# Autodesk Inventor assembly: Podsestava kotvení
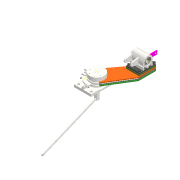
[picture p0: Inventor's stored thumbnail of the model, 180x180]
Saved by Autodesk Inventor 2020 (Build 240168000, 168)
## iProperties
Created: 2025-04
Part Number: Podsestava kotvení
Document SubType Name: Assembly
Designer: doma
Author: doma
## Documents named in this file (13)
- C:\Users\doma\Desktop\Pásovka záloha\Workgroups\NotInProject\Podsestava kotvení.iam
- C:\Users\doma\Desktop\Pásovka záloha\Workgroups\NotInProject\Deska kotevní.ipt
- C:\Users\doma\Desktop\Pásovka záloha\Workgroups\NotInProject\Středící kroužek.ipt
- C:\Users\doma\Desktop\Pásovka záloha\Workgroups\NotInProject\Doraz otočný.ipt
- C:\Users\doma\Desktop\Pásovka záloha\Workgroups\NotInProject\Svařenec horní části středu.iam
- C:\Users\doma\Desktop\Pásovka záloha\Workgroups\NotInProject\Domeček ax ložiska středu.ipt
- C:\Users\doma\Desktop\Pásovka záloha\Workgroups\NotInProject\Matice  středu.ipt
- C:\Users\doma\Desktop\Pásovka záloha\Workgroups\NotInProject\Tyč.ipt
- C:\Users\doma\Documents\Inventor\Content Center Files\R2020\cs-CZ\ISO 4762(2)\ISO 4762 - M5 x 30ISO.ipt
- C:\Users\doma\Desktop\Pásovka záloha\Workgroups\NotInProject\Podsestava otočné rameno.iam
- C:\Users\doma\Documents\Inventor\Content Center Files\R2020\cs-CZ\CSN 02 1741\CSN 02 1741 - 6.ipt
- C:\Users\doma\Desktop\Pásovka záloha\Libraries\Content Center Files\cs-CZ\CSN 02 4730\CSN 02 4730 - 511 04 - 20 x 35 x 10.ipt
- C:\Users\doma\Documents\Inventor\Content Center Files\R2020\cs-CZ\ISO 4762(2)\ISO 4762 - M6 x 45ISO.ipt
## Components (19 placed, 12 different names)
1. Deska kotevní:1 — Úhel:2, Proti sobě:17
2. Středící kroužek:1
3. Doraz otočný:1
4. Svařenec horní části středu:1 [sub-assembly] — Proti sobě:18
5. Domeček ax ložiska středu:1 — Proti sobě:19
6. Matice  středu:1
7. Tyč:1
8. ISO 4762 M5 x 30:1
9. ISO 4762 M5 x 30:2
10. Podsestava otočné rameno:1 [sub-assembly] — Úhel:2
11. CSN 02 1741 6:1
12. CSN 02 1741 6:2
13. CSN 02 1741 6:3
14. CSN 02 1741 6:4
15. ISO 4762 M6 x 45:2
16. ISO 4762 M6 x 45:1
17. ISO 4762 M6 x 45:3
18. ISO 4762 M6 x 45:4
19. CSN 02 4730 511 04 - 20 x 35 x 10:1 — Proti sobě:17, Proti sobě:18, Proti sobě:19
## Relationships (4: Mate 3, Angle 1)
- Úhel:2 [Angle]: Deska kotevní:1 ↔ Podsestava otočné rameno:1
- Proti sobě:17 [Mate]: Deska kotevní:1 ↔ CSN 02 4730 511 04 - 20 x 35 x 10:1
- Proti sobě:18 [Mate]: Svařenec horní části středu:1 ↔ CSN 02 4730 511 04 - 20 x 35 x 10:1
- Proti sobě:19 [Mate]: Domeček ax ložiska středu:1 ↔ CSN 02 4730 511 04 - 20 x 35 x 10:1
## Named parameters: d0_d4 = 0, d1_d5 = 0
